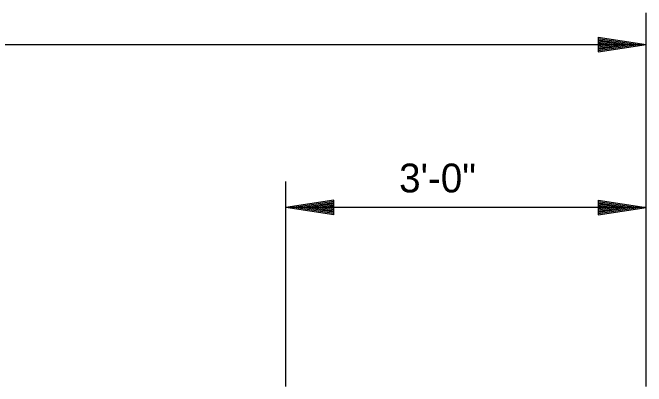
# Model space of a CAD drawing. Extents: x 635488 to 635865, y 290537 to 290973.
# Drawn here: x 635737.65 to 635750.83, y 290613.36 to 290621.14 of the extents above; entities that cross this region are included whole.
import ezdxf

# ---------------------------------------------------------------- set-up
doc = ezdxf.new("R2010")
doc.units = 0
doc.layers.add('Default', color=7, linetype='Continuous')

msp = doc.modelspace()

# ---------------------------------------------------------------- linework, layer by layer
at = {"layer": 'Default'}
for p, q in [((635750.831, 290613.362), (635750.831, 290621.142)), ((635749.832, 290620.63), (635750.832, 290620.48)), ((635749.832, 290620.63), (635749.832, 290620.33)), ((635749.832, 290620.605), (635750.664, 290620.48)), ((635749.832, 290620.58), (635750.492, 290620.48)), ((635749.832, 290620.555), (635750.327, 290620.48)), ((635749.832, 290620.53), (635750.157, 290620.48)), ((635709.583, 290620.481), (635750.831, 290620.481)), ((635749.832, 290620.505), (635749.989, 290620.48)), ((635749.832, 290620.33), (635750.832, 290620.48)), ((635749.832, 290620.433), (635750.157, 290620.48)), ((635749.832, 290620.38), (635750.492, 290620.48)), ((635749.832, 290620.355), (635750.664, 290620.48)), ((635749.832, 290620.405), (635750.327, 290620.48)), ((635749.832, 290620.458), (635749.989, 290620.48)), ((635743.331, 290613.362), (635743.331, 290617.625)), ((635750.831, 290613.362), (635750.831, 290617.625)), ((635750.831, 290613.362), (635750.831, 290617.625)), ((635744.332, 290617.236), (635743.332, 290617.086)), ((635744.332, 290616.936), (635744.332, 290617.236)), ((635749.831, 290617.236), (635750.831, 290617.086)), ((635749.831, 290617.236), (635749.831, 290616.936)), ((635750.831, 290617.086), (635743.331, 290617.086)), ((635744.332, 290616.936), (635743.332, 290617.086)), ((635744.332, 290617.211), (635743.5, 290617.086)), ((635744.332, 290616.961), (635743.5, 290617.086)), ((635744.332, 290617.186), (635743.67, 290617.086)), ((635744.332, 290616.986), (635743.67, 290617.086)), ((635744.332, 290617.161), (635743.837, 290617.086)), ((635744.332, 290617.011), (635743.837, 290617.086)), ((635744.332, 290617.136), (635744.007, 290617.086)), ((635744.332, 290617.038), (635744.007, 290617.086)), ((635744.332, 290617.111), (635744.175, 290617.086)), ((635744.332, 290617.063), (635744.175, 290617.086)), ((635749.831, 290617.211), (635750.663, 290617.086)), ((635749.831, 290617.186), (635750.491, 290617.086)), ((635749.831, 290617.161), (635750.326, 290617.086)), ((635749.831, 290617.136), (635750.156, 290617.086)), ((635749.831, 290617.111), (635749.988, 290617.086)), ((635749.831, 290616.936), (635750.831, 290617.086)), ((635749.831, 290617.039), (635750.156, 290617.086)), ((635749.831, 290616.986), (635750.491, 290617.086)), ((635749.831, 290616.961), (635750.663, 290617.086)), ((635749.831, 290617.011), (635750.326, 290617.086)), ((635749.831, 290617.064), (635749.988, 290617.086))]:
    msp.add_line(p, q, dxfattribs=at)

# ---------------------------------------------------------------- texts
msp.add_text('3\'-0"', height=0.6, dxfattribs=at).set_placement((635745.69, 290617.4))

doc.saveas('drawing.dxf')
